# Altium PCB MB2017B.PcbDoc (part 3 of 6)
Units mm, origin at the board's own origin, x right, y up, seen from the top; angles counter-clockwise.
Board outline 148.19 x 169.19 mm, 4 copper layers (Top Layer, Mid Layer 1, Mid Layer 2, Bottom Layer), stack 1.498 mm thick; 458 components, 208 nets, 1223 pads, 6162 vias.
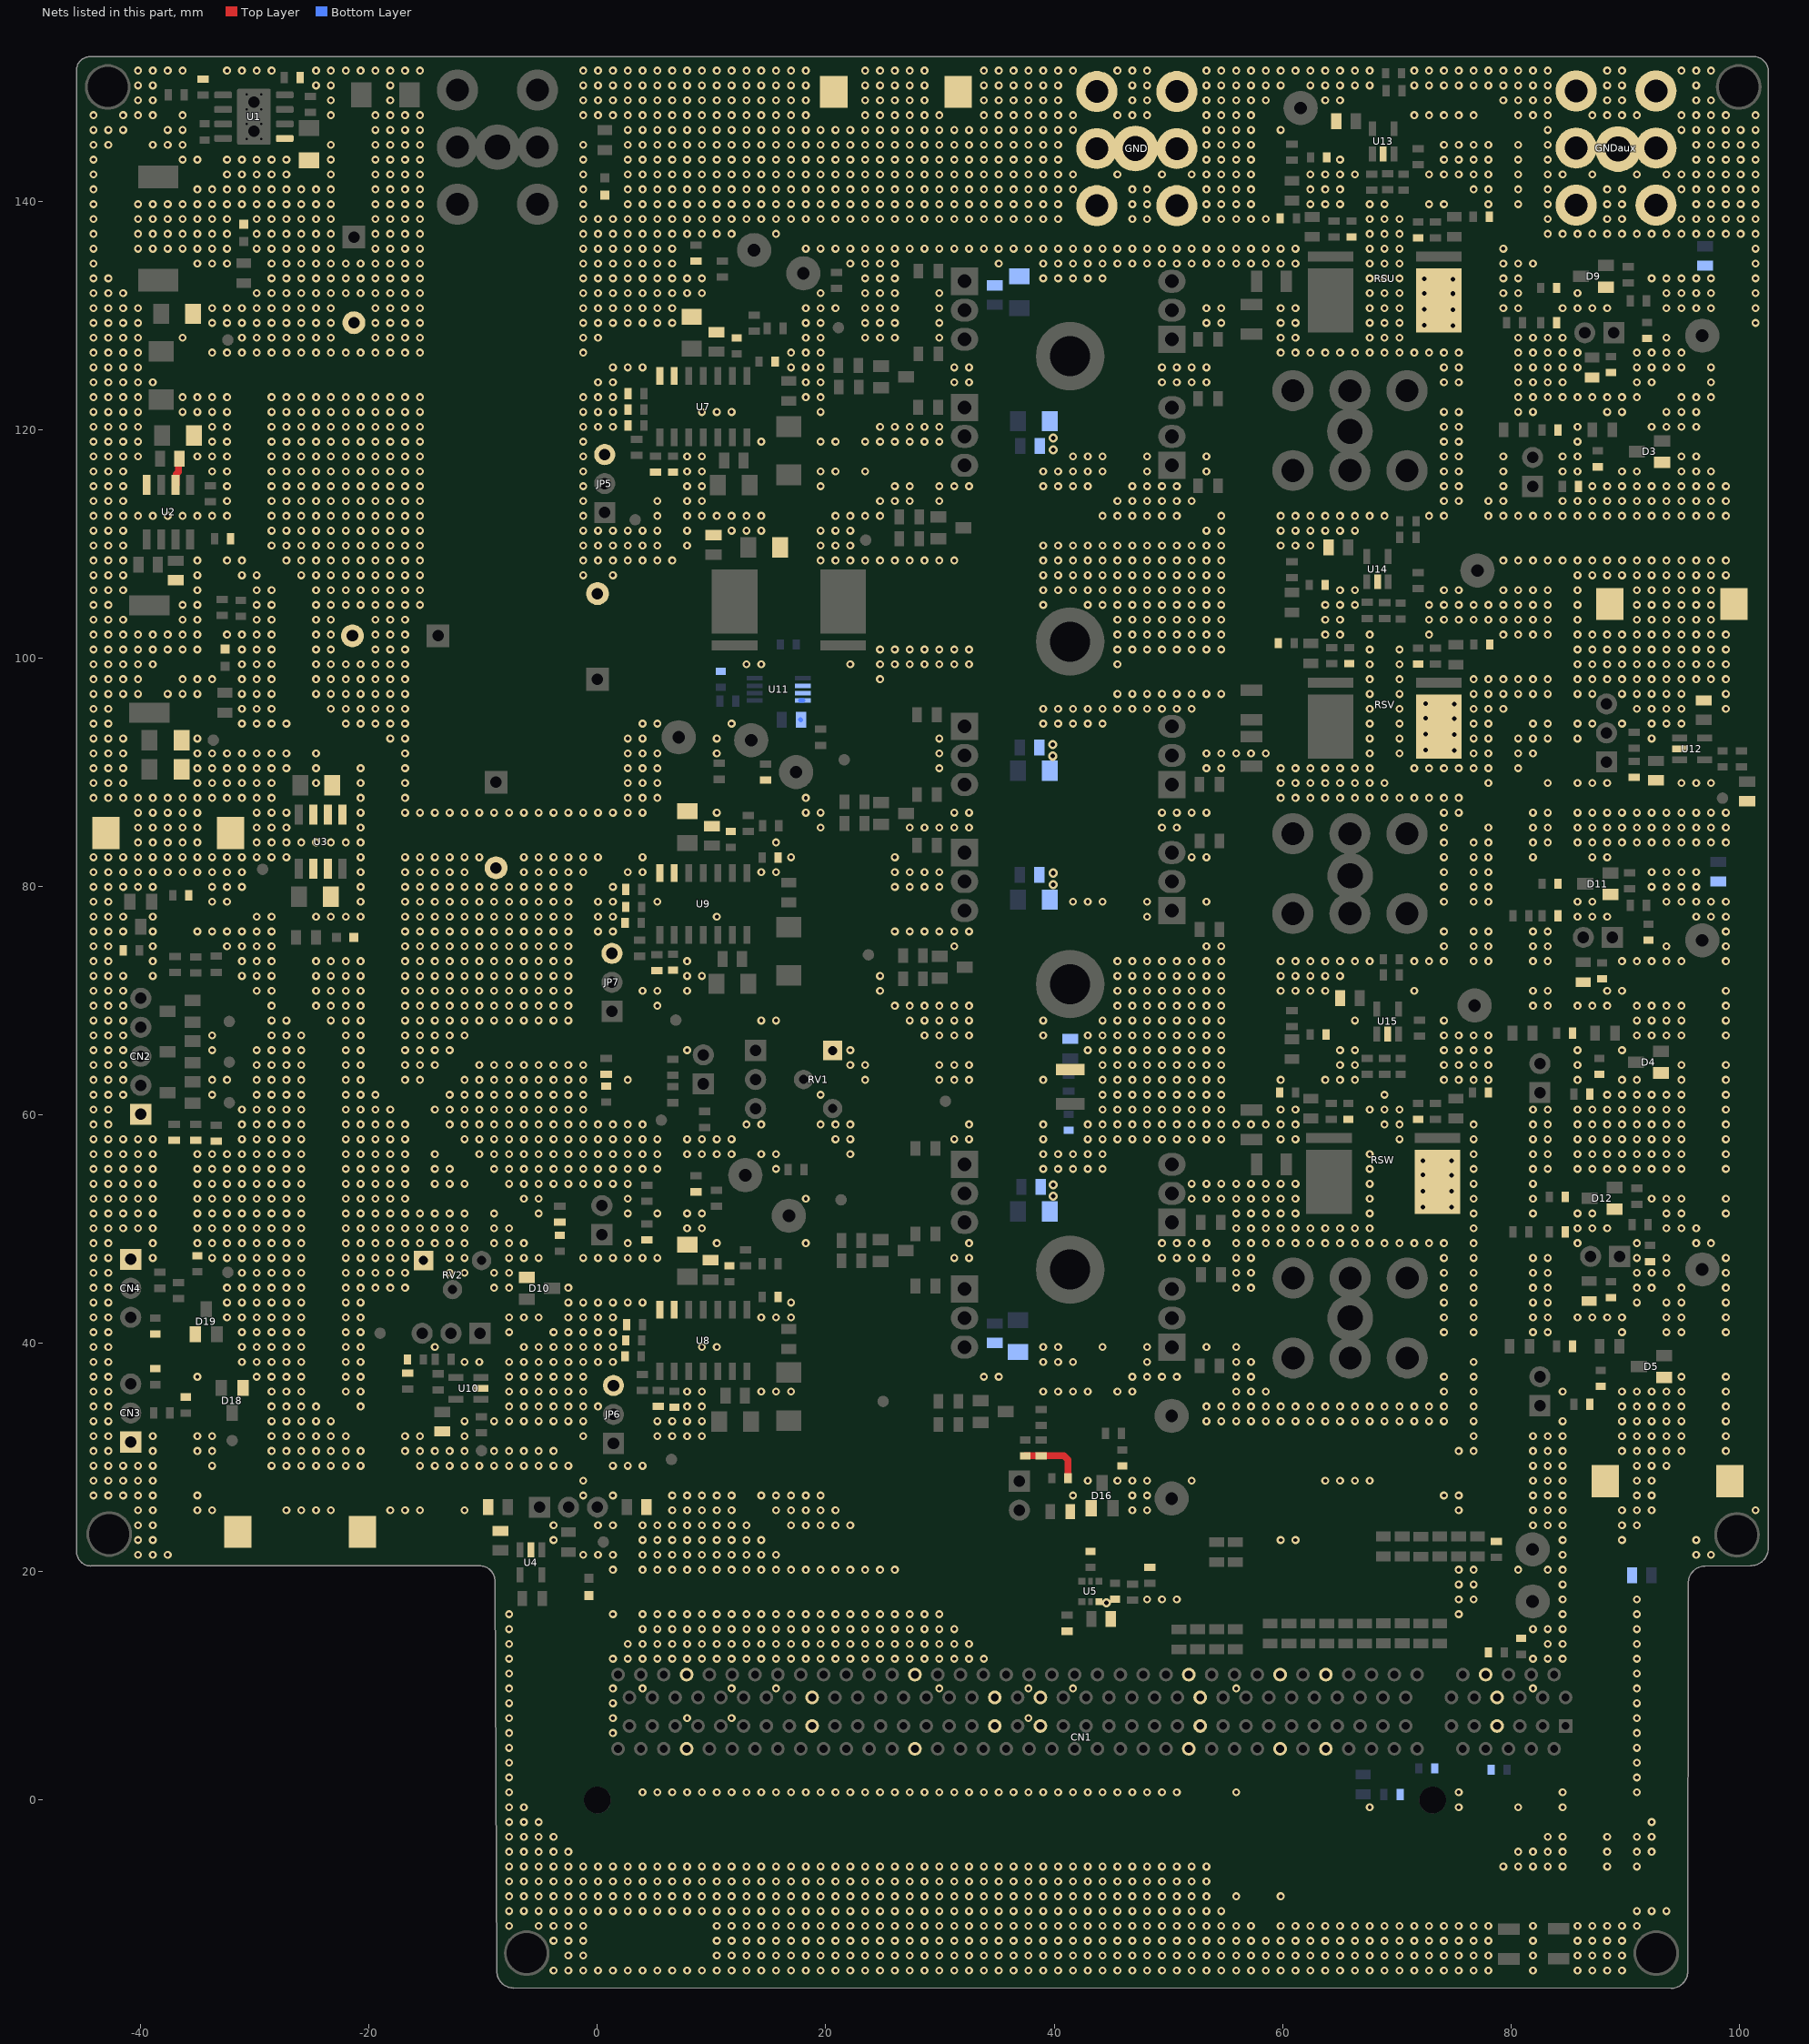
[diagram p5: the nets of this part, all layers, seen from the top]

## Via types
v1: diameter 0.7, hole 0.35, Top Layer to Bottom Layer, tented both sides, 5935 vias
v2: diameter 0.8, hole 0.4, Top Layer to Bottom Layer, tented both sides, 216 vias
v3: diameter 1, hole 0.5, Top Layer to Bottom Layer, tented both sides, 9 vias
v4: diameter 0.8, hole 0.4, Top Layer to Bottom Layer, 2 vias

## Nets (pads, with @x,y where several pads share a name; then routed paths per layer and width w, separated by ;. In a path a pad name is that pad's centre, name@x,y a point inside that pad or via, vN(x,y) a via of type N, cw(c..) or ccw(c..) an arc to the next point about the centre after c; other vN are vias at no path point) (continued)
GND: (continued)
  other v1: -3.853,-14.916 -2.553,-14.916 -1.253,-14.916 0.047,-14.916 1.347,-14.916 2.647,-14.916 3.947,-14.916 5.247,-14.916 6.547,-14.916 7.847,-14.916 9.147,-14.916 10.447,-14.916 11.747,-14.916 13.047,-14.916 14.347,-14.916 15.647,-14.916 16.947,-14.916 18.247,-14.916 19.547,-14.916 20.847,-14.916 22.147,-14.916 23.447,-14.916 24.747,-14.916 26.047,-14.916 27.347,-14.916 28.647,-14.916 29.947,-14.916 31.247,-14.916 32.547,-14.916 33.847,-14.916 35.147,-14.916 36.447,-14.916 37.747,-14.916 39.047,-14.916 40.347,-14.916 41.647,-14.916 42.947,-14.916 44.247,-14.916 45.547,-14.916 46.847,-14.916 48.147,-14.916 49.447,-14.916 50.747,-14.916 52.047,-14.916 53.347,-14.916 54.647,-14.916 55.947,-14.916 57.247,-14.916 58.547,-14.916 59.847,-14.916 61.147,-14.916 62.447,-14.916 63.747,-14.916 65.047,-14.916 66.347,-14.916 67.647,-14.916 68.947,-14.916 70.247,-14.916 71.547,-14.916 72.847,-14.916 74.147,-14.916 75.447,-14.916 76.747,-14.916 78.047,-14.916 81.947,-14.916 85.847,-14.916 87.147,-14.916 88.447,-14.916 89.747,-14.916 -2.553,-13.616 -1.253,-13.616 10.447,-13.616 11.747,-13.616 13.047,-13.616 14.347,-13.616 15.647,-13.616 16.947,-13.616 18.247,-13.616 19.547,-13.616 20.847,-13.616 22.147,-13.616 23.447,-13.616 24.747,-13.616 26.047,-13.616 27.347,-13.616 28.647,-13.616 29.947,-13.616 31.247,-13.616 32.547,-13.616 33.847,-13.616 35.147,-13.616 36.447,-13.616 37.747,-13.616 39.047,-13.616 40.347,-13.616 41.647,-13.616 42.947,-13.616 44.247,-13.616 45.547,-13.616 46.847,-13.616 48.147,-13.616 49.447,-13.616 50.747,-13.616 52.047,-13.616 53.347,-13.616 54.647,-13.616 55.947,-13.616 57.247,-13.616 58.547,-13.616 59.847,-13.616 61.147,-13.616 62.447,-13.616 63.747,-13.616 65.047,-13.616 66.347,-13.616 67.647,-13.616 68.947,-13.616 70.247,-13.616 71.547,-13.616 72.847,-13.616 74.147,-13.616 75.447,-13.616 76.747,-13.616 78.047,-13.616 81.947,-13.616 85.847,-13.616 87.147,-13.616 88.447,-13.616 89.747,-13.616 -3.853,-12.316 -2.553,-12.316 -1.253,-12.316 10.447,-12.316 11.747,-12.316 13.047,-12.316 14.347,-12.316 15.647,-12.316 16.947,-12.316 18.247,-12.316 19.547,-12.316 20.847,-12.316 22.147,-12.316 23.447,-12.316 24.747,-12.316 26.047,-12.316 27.347,-12.316 28.647,-12.316 29.947,-12.316 31.247,-12.316 32.547,-12.316 33.847,-12.316 35.147,-12.316 36.447,-12.316 37.747,-12.316 39.047,-12.316 40.347,-12.316 41.647,-12.316 42.947,-12.316 44.247,-12.316 45.547,-12.316 46.847,-12.316 48.147,-12.316 49.447,-12.316 50.747,-12.316 52.047,-12.316 53.347,-12.316 54.647,-12.316 55.947,-12.316 57.247,-12.316 58.547,-12.316 59.847,-12.316 61.147,-12.316 62.447,-12.316 63.747,-12.316 65.047,-12.316 66.347,-12.316 67.647,-12.316 68.947,-12.316 70.247,-12.316 71.547,-12.316 72.847,-12.316 74.147,-12.316 75.447,-12.316 76.747,-12.316 78.047,-12.316 81.947,-12.316 85.847,-12.316 87.147,-12.316 88.447,-12.316 89.747,-12.316 -7.753,-11.016 -5.153,-11.016 -3.853,-11.016 -2.553,-11.016 -1.253,-11.016 10.447,-11.016 11.747,-11.016 13.047,-11.016 14.347,-11.016 15.647,-11.016 16.947,-11.016 18.247,-11.016 19.547,-11.016 20.847,-11.016 22.147,-11.016 23.447,-11.016 24.747,-11.016 26.047,-11.016 27.347,-11.016 28.647,-11.016 29.947,-11.016 31.247,-11.016 32.547,-11.016 33.847,-11.016 35.147,-11.016 36.447,-11.016 37.747,-11.016 39.047,-11.016 40.347,-11.016 41.647,-11.016 42.947,-11.016 44.247,-11.016 45.547,-11.016 46.847,-11.016 48.147,-11.016 49.447,-11.016 50.747,-11.016 52.047,-11.016 53.347,-11.016 54.647,-11.016 55.947,-11.016 57.247,-11.016 59.847,-11.016 61.147,-11.016 62.447,-11.016 63.747,-11.016 65.047,-11.016 66.347,-11.016 67.647,-11.016 68.947,-11.016 70.247,-11.016 71.547,-11.016 72.847,-11.016 74.147,-11.016 75.447,-11.016 76.747,-11.016 78.047,-11.016 81.947,-11.016 85.847,-11.016 87.147,-11.016 88.447,-11.016 89.747,-11.016 91.047,-11.016 -7.753,-9.716 -6.453,-9.716 -5.153,-9.716 -3.853,-9.716 -2.553,-9.716 -1.253,-9.716 0.047,-9.716 1.347,-9.716 2.647,-9.716 3.947,-9.716 5.247,-9.716 6.547,-9.716 7.847,-9.716 9.147,-9.716 10.447,-9.716 11.747,-9.716 13.047,-9.716 14.347,-9.716 15.647,-9.716 16.947,-9.716 18.247,-9.716 19.547,-9.716 20.847,-9.716 22.147,-9.716 23.447,-9.716 24.747,-9.716 26.047,-9.716 27.347,-9.716 28.647,-9.716 29.947,-9.716 31.247,-9.716 32.547,-9.716 33.847,-9.716 35.147,-9.716 36.447,-9.716 37.747,-9.716 39.047,-9.716 40.347,-9.716 41.647,-9.716 42.947,-9.716 44.247,-9.716 45.547,-9.716 46.847,-9.716 48.147,-9.716 49.447,-9.716 50.747,-9.716 52.047,-9.716 53.347,-9.716 54.647,-9.716 91.047,-9.716 92.347,-9.716 93.647,-9.716 -7.753,-8.416 -6.453,-8.416 -5.153,-8.416 -3.853,-8.416 -2.553,-8.416 -1.253,-8.416 0.047,-8.416 1.347,-8.416 2.647,-8.416 3.947,-8.416 5.247,-8.416 6.547,-8.416 7.847,-8.416 9.147,-8.416 10.447,-8.416 11.747,-8.416 13.047,-8.416 14.347,-8.416 15.647,-8.416 16.947,-8.416 18.247,-8.416 19.547,-8.416 20.847,-8.416 22.147,-8.416 23.447,-8.416 24.747,-8.416 26.047,-8.416 27.347,-8.416 28.647,-8.416 29.947,-8.416 31.247,-8.416 32.547,-8.416 33.847,-8.416 35.147,-8.416 36.447,-8.416 37.747,-8.416 39.047,-8.416 40.347,-8.416 41.647,-8.416 42.947,-8.416 44.247,-8.416 45.547,-8.416 46.847,-8.416 48.147,-8.416 49.447,-8.416 50.747,-8.416 52.047,-8.416 53.347,-8.416 55.947,-8.416 59.847,-8.416 -7.753,-7.116 -6.453,-7.116 -5.153,-7.116 -3.853,-7.116 -2.553,-7.116 -1.253,-7.116 0.047,-7.116 1.347,-7.116 2.647,-7.116 3.947,-7.116 5.247,-7.116 6.547,-7.116 7.847,-7.116 9.147,-7.116 10.447,-7.116 11.747,-7.116 13.047,-7.116 14.347,-7.116 15.647,-7.116 16.947,-7.116 18.247,-7.116 19.547,-7.116 20.847,-7.116 22.147,-7.116 23.447,-7.116 24.747,-7.116 26.047,-7.116 27.347,-7.116 28.647,-7.116 29.947,-7.116 31.247,-7.116 32.547,-7.116 33.847,-7.116 35.147,-7.116 36.447,-7.116 37.747,-7.116 39.047,-7.116 40.347,-7.116 41.647,-7.116 42.947,-7.116 44.247,-7.116 45.547,-7.116 46.847,-7.116 48.147,-7.116 49.447,-7.116 50.747,-7.116 52.047,-7.116 53.347,-7.116 -7.753,-5.816 -6.453,-5.816 -5.153,-5.816 -3.853,-5.816 -2.553,-5.816 -1.253,-5.816 0.047,-5.816 1.347,-5.816 2.647,-5.816 3.947,-5.816 5.247,-5.816 6.547,-5.816 7.847,-5.816 9.147,-5.816 10.447,-5.816 11.747,-5.816 13.047,-5.816 14.347,-5.816 15.647,-5.816 16.947,-5.816 18.247,-5.816 19.547,-5.816 20.847,-5.816 22.147,-5.816 23.447,-5.816 24.747,-5.816 26.047,-5.816 27.347,-5.816 28.647,-5.816 29.947,-5.816 31.247,-5.816 32.547,-5.816 33.847,-5.816 35.147,-5.816 36.447,-5.816 37.747,-5.816 39.047,-5.816 40.347,-5.816 41.647,-5.816 42.947,-5.816 44.247,-5.816 45.547,-5.816 46.847,-5.816 48.147,-5.816 49.447,-5.816 50.747,-5.816 52.047,-5.816 53.347,-5.816 79.347,-5.816 80.647,-5.816 81.947,-5.816 83.247,-5.816 84.547,-5.816 88.447,-5.816 91.047,-5.816 -7.753,-4.516 -6.453,-4.516 -5.153,-4.516 -3.853,-4.516 -2.553,-4.516 80.647,-4.516 81.947,-4.516 83.247,-4.516 84.547,-4.516 88.447,-4.516 91.047,-4.516 92.347,-4.516 -7.753,-3.216 -6.453,-3.216 -5.153,-3.216 -3.853,-3.216 83.247,-3.216 84.547,-3.216 88.447,-3.216 91.047,-3.216 92.347,-3.216 -7.753,-1.916 -6.453,-1.916 -5.153,-1.916 92.347,-1.916 -7.753,-0.616 -6.453,-0.616 67.647,-0.616 75.447,-0.616 80.647,-0.616 84.547,-0.616 -7.753,0.684 3.947,0.684 5.247,0.684 6.547,0.684 7.847,0.684 9.147,0.684 10.447,0.684 11.747,0.684 13.047,0.684 14.347,0.684 15.647,0.684 16.947,0.684 18.247,0.684 19.547,0.684 20.847,0.684 22.147,0.684 23.447,0.684 24.747,0.684 26.047,0.684 27.347,0.684 28.647,0.684 29.947,0.684 31.247,0.684 32.547,0.684 33.847,0.684 35.147,0.684 36.447,0.684 37.747,0.684 39.047,0.684 40.347,0.684 41.647,0.684 42.947,0.684 44.247,0.684 45.547,0.684 46.847,0.684 48.147,0.684 49.447,0.684 50.747,0.684 55.947,0.684 75.447,0.684 84.547,0.684 91.047,0.684 -7.753,1.984 91.047,1.984 -7.753,3.284 91.047,3.284 -7.753,4.584 91.047,4.584 -7.753,5.884 1.347,5.884 91.047,5.884 -7.753,7.184 1.347,7.184 7.847,7.184 11.747,7.184 37.747,7.184 91.047,7.184 -7.753,8.484 1.347,8.484 91.047,8.484 -7.753,9.784 1.347,9.784 3.947,9.784 11.747,9.784 15.647,9.784 29.947,9.784 37.747,9.784 41.647,9.784 55.947,9.784 81.947,9.784 91.047,9.784 -7.753,11.084 91.047,11.084 -7.753,12.384 1.347,12.384 2.647,12.384 3.947,12.384 5.247,12.384 6.547,12.384 7.847,12.384 9.147,12.384 10.447,12.384 11.747,12.384 13.047,12.384 14.347,12.384 15.647,12.384 16.947,12.384 18.247,12.384 19.547,12.384 20.847,12.384 22.147,12.384 23.447,12.384 24.747,12.384 26.047,12.384 27.347,12.384 28.647,12.384 29.947,12.384 31.247,12.384 32.547,12.384 33.847,12.384 81.947,12.384 83.247,12.384 84.547,12.384 91.047,12.384 -7.753,13.684 2.647,13.684 3.947,13.684 5.247,13.684 6.547,13.684 7.847,13.684 9.147,13.684 10.447,13.684 11.747,13.684 13.047,13.684 14.347,13.684 15.647,13.684 16.947,13.684 18.247,13.684 19.547,13.684 20.847,13.684 22.147,13.684 23.447,13.684 24.747,13.684 26.047,13.684 27.347,13.684 28.647,13.684 29.947,13.684 31.247,13.684 32.547,13.684 83.247,13.684 84.547,13.684 91.047,13.684 -7.753,14.984 3.947,14.984 5.247,14.984 6.547,14.984 7.847,14.984 9.147,14.984 10.447,14.984 11.747,14.984 13.047,14.984 14.347,14.984 15.647,14.984 16.947,14.984 18.247,14.984 19.547,14.984 20.847,14.984 22.147,14.984 23.447,14.984 24.747,14.984 26.047,14.984 27.347,14.984 28.647,14.984 29.947,14.984 31.247,14.984 81.947,14.984 83.247,14.984 84.547,14.984 91.047,14.984 -7.753,16.284 1.347,16.284 3.947,16.284 5.247,16.284 6.547,16.284 7.847,16.284 9.147,16.284 10.447,16.284 11.747,16.284 13.047,16.284 14.347,16.284 15.647,16.284 16.947,16.284 18.247,16.284 19.547,16.284 20.847,16.284 22.147,16.284 23.447,16.284 24.747,16.284 26.047,16.284 27.347,16.284 28.647,16.284 29.947,16.284 75.447,16.284 84.547,16.284 91.047,16.284 48.147,17.584 49.447,17.584 50.747,17.584 75.447,17.584 76.747,17.584 84.547,17.584 91.047,17.584 75.447,18.884 76.747,18.884 84.547,18.884 1.347,20.184 3.947,20.184 5.247,20.184 6.547,20.184 7.847,20.184 9.147,20.184 10.447,20.184 11.747,20.184 13.047,20.184 14.347,20.184 15.647,20.184 16.947,20.184 18.247,20.184 19.547,20.184 20.847,20.184 22.147,20.184 23.447,20.184 24.747,20.184 26.047,20.184 75.447,20.184 76.747,20.184 80.647,20.184 83.247,20.184 84.547,20.184 -40.253,21.484 -38.953,21.484 -37.653,21.484 -1.253,21.484 0.047,21.484 1.347,21.484 3.947,21.484 5.247,21.484 6.547,21.484 7.847,21.484 9.147,21.484 10.447,21.484 11.747,21.484 13.047,21.484 14.347,21.484 15.647,21.484 84.547,21.484 96.247,21.484 97.547,21.484 -40.253,22.784 -38.953,22.784 -3.853,22.784 3.947,22.784 5.247,22.784 6.547,22.784 7.847,22.784 9.147,22.784 10.447,22.784 11.747,22.784 13.047,22.784 14.347,22.784 59.847,22.784 61.147,22.784 84.547,22.784 89.747,22.784 96.247,22.784 -40.253,24.084 -38.953,24.084 -3.853,24.084 0.047,24.084 1.347,24.084 3.947,24.084 5.247,24.084 6.547,24.084 7.847,24.084 9.147,24.084 10.447,24.084 11.747,24.084 13.047,24.084 16.947,24.084 18.247,24.084 19.547,24.084 20.847,24.084 22.147,24.084 81.947,24.084 83.247,24.084 84.547,24.084 89.747,24.084 91.047,24.084 -40.253,25.384 -38.953,25.384 -35.053,25.384 -33.753,25.384 -27.253,25.384 -25.953,25.384 -24.653,25.384 -23.353,25.384 -18.153,25.384 -16.853,25.384 -15.553,25.384 -11.653,25.384 6.547,25.384 7.847,25.384 9.147,25.384 10.447,25.384 11.747,25.384 15.647,25.384 16.947,25.384 18.247,25.384 19.547,25.384 20.847,25.384 46.847,25.384 48.147,25.384 75.447,25.384 81.947,25.384 83.247,25.384 84.547,25.384 89.747,25.384 91.047,25.384 92.347,25.384 101.447,25.384 -44.153,26.684 -42.853,26.684 -41.553,26.684 -40.253,26.684 -38.953,26.684 -35.053,26.684 -1.253,26.684 1.347,26.684 6.547,26.684 7.847,26.684 9.147,26.684 10.447,26.684 11.747,26.684 14.347,26.684 15.647,26.684 16.947,26.684 18.247,26.684 19.547,26.684 41.647,26.684 46.847,26.684 48.147,26.684 74.147,26.684 75.447,26.684 81.947,26.684 83.247,26.684 84.547,26.684 91.047,26.684 92.347,26.684 -44.153,27.984 -42.853,27.984 -41.553,27.984 -40.253,27.984 -38.953,27.984 -1.253,27.984 42.947,27.984 45.547,27.984 46.847,27.984 48.147,27.984 52.047,27.984 63.747,27.984 65.047,27.984 66.347,27.984 67.647,27.984 81.947,27.984 83.247,27.984 84.547,27.984 91.047,27.984 92.347,27.984 -44.153,29.284 -42.853,29.284 -41.553,29.284 -40.253,29.284 -38.953,29.284 -33.753,29.284 -28.553,29.284 -27.253,29.284 -25.953,29.284 -24.653,29.284 -23.353,29.284 -22.053,29.284 -20.753,29.284 -15.553,29.284 -14.253,29.284 -12.953,29.284 -11.653,29.284 -10.353,29.284 -9.053,29.284 -7.753,29.284 -6.453,29.284 -5.153,29.284 -3.853,29.284 -2.553,29.284 1.347,29.284 2.647,29.284 3.947,29.284 81.947,29.284 83.247,29.284 84.547,29.284 91.047,29.284 92.347,29.284 93.647,29.284 -44.153,30.584 -42.853,30.584 -38.953,30.584 -35.053,30.584 -33.753,30.584 -28.553,30.584 -27.253,30.584 -25.953,30.584 -24.653,30.584 -23.353,30.584 -22.053,30.584 -20.753,30.584 -16.853,30.584 -15.553,30.584 -14.253,30.584 -12.953,30.584 -11.653,30.584 -9.053,30.584 -7.753,30.584 -6.453,30.584 -5.153,30.584 -3.853,30.584 75.447,30.584 76.747,30.584 81.947,30.584 83.247,30.584 84.547,30.584 89.747,30.584 91.047,30.584 92.347,30.584 93.647,30.584 94.947,30.584 98.847,30.584 -44.153,31.884 -42.853,31.884 -38.953,31.884 -35.053,31.884 -33.753,31.884 -28.553,31.884 -27.253,31.884 -25.953,31.884 -24.653,31.884 -23.353,31.884 -22.053,31.884 -16.853,31.884 -15.553,31.884 -11.653,31.884 -1.253,31.884 5.247,31.884 6.547,31.884 7.847,31.884 9.147,31.884 76.747,31.884 81.947,31.884 83.247,31.884 84.547,31.884 89.747,31.884 91.047,31.884 92.347,31.884 93.647,31.884 94.947,31.884 98.847,31.884 -44.153,33.184 -42.853,33.184 -28.553,33.184 -27.253,33.184 -25.953,33.184 -24.653,33.184 -23.353,33.184 -11.653,33.184 -9.053,33.184 -7.753,33.184 -6.453,33.184 -5.153,33.184 -3.853,33.184 -2.553,33.184 -1.253,33.184 5.247,33.184 6.547,33.184 7.847,33.184 9.147,33.184 53.347,33.184 54.647,33.184 55.947,33.184 57.247,33.184 58.547,33.184 59.847,33.184 61.147,33.184 62.447,33.184 63.747,33.184 65.047,33.184 66.347,33.184 67.647,33.184 68.947,33.184 70.247,33.184 71.547,33.184 72.847,33.184 74.147,33.184 76.747,33.184 84.547,33.184 89.747,33.184 91.047,33.184 92.347,33.184 93.647,33.184 94.947,33.184 98.847,33.184 -44.153,34.484 -42.853,34.484 -28.553,34.484 -27.253,34.484 -25.953,34.484 -24.653,34.484 -20.753,34.484 -7.753,34.484 -6.453,34.484 -5.153,34.484 -3.853,34.484 -2.553,34.484 -1.253,34.484 0.047,34.484 7.847,34.484 9.147,34.484 53.347,34.484 54.647,34.484 55.947,34.484 57.247,34.484 58.547,34.484 59.847,34.484 61.147,34.484 62.447,34.484 63.747,34.484 65.047,34.484 66.347,34.484 67.647,34.484 68.947,34.484 70.247,34.484 71.547,34.484 72.847,34.484 74.147,34.484 76.747,34.484 89.747,34.484 91.047,34.484 92.347,34.484 93.647,34.484 94.947,34.484 98.847,34.484 -44.153,35.784 -42.853,35.784 -28.553,35.784 -27.253,35.784 -25.953,35.784 -22.053,35.784 -20.753,35.784 -7.753,35.784 -6.453,35.784 -5.153,35.784 -3.853,35.784 -2.553,35.784 -1.253,35.784 7.847,35.784 9.147,35.784 14.347,35.784 15.647,35.784 16.947,35.784 39.047,35.784 40.347,35.784 41.647,35.784 42.947,35.784 45.547,35.784 46.847,35.784 55.947,35.784 57.247,35.784 58.547,35.784 74.147,35.784 76.747,35.784 84.547,35.784 89.747,35.784 91.047,35.784 92.347,35.784 93.647,35.784 94.947,35.784 98.847,35.784 -44.153,37.084 -42.853,37.084 -35.053,37.084 -29.853,37.084 -28.553,37.084 -27.253,37.084 -25.953,37.084 -22.053,37.084 -20.753,37.084 -7.753,37.084 -6.453,37.084 -5.153,37.084 -3.853,37.084 -2.553,37.084 -1.253,37.084 33.847,37.084 35.147,37.084 46.847,37.084 48.147,37.084 49.447,37.084 50.747,37.084 55.947,37.084 57.247,37.084 74.147,37.084 76.747,37.084 94.947,37.084 98.847,37.084 -44.153,38.384 -42.853,38.384 -31.153,38.384 -29.853,38.384 -28.553,38.384 -27.253,38.384 -25.953,38.384 -22.053,38.384 -20.753,38.384 -11.653,38.384 -10.353,38.384 -7.753,38.384 -6.453,38.384 -5.153,38.384 -3.853,38.384 -2.553,38.384 -1.253,38.384 0.047,38.384 1.347,38.384 39.047,38.384 40.347,38.384 41.647,38.384 48.147,38.384 55.947,38.384 57.247,38.384 76.747,38.384 -44.153,39.684 -42.853,39.684 -31.153,39.684 -29.853,39.684 -28.553,39.684 -27.253,39.684 -25.953,39.684 -22.053,39.684 -20.753,39.684 -14.253,39.684 -6.453,39.684 -5.153,39.684 -3.853,39.684 -2.553,39.684 -1.253,39.684 0.047,39.684 1.347,39.684 9.147,39.684 10.447,39.684 39.047,39.684 40.347,39.684 44.247,39.684 48.147,39.684 53.347,39.684 55.947,39.684 -44.153,40.984 -42.853,40.984 -31.153,40.984 -29.853,40.984 -28.553,40.984 -27.253,40.984 -25.953,40.984 -22.053,40.984 -20.753,40.984 -7.753,40.984 -3.853,40.984 -2.553,40.984 -1.253,40.984 0.047,40.984 1.347,40.984 74.147,40.984 76.747,40.984 81.947,40.984 83.247,40.984 89.747,40.984 93.647,40.984 94.947,40.984 98.847,40.984 -44.153,42.284 -42.853,42.284 -32.453,42.284 -31.153,42.284 -29.853,42.284 -28.553,42.284 -27.253,42.284 -25.953,42.284 -22.053,42.284 -20.753,42.284 -7.753,42.284 -6.453,42.284 -5.153,42.284 -2.553,42.284 -1.253,42.284 0.047,42.284 1.347,42.284 14.347,42.284 15.647,42.284 16.947,42.284 74.147,42.284 76.747,42.284 81.947,42.284 83.247,42.284 85.847,42.284 87.147,42.284 88.447,42.284 89.747,42.284 93.647,42.284 94.947,42.284 98.847,42.284 -44.153,43.584 -42.853,43.584 -32.453,43.584 -31.153,43.584 -29.853,43.584 -28.553,43.584 -27.253,43.584 -25.953,43.584 -22.053,43.584 -20.753,43.584 -2.553,43.584 -1.253,43.584 0.047,43.584 1.347,43.584 2.647,43.584 3.947,43.584 16.947,43.584 74.147,43.584 76.747,43.584 81.947,43.584 83.247,43.584 91.047,43.584 93.647,43.584 94.947,43.584 98.847,43.584 -44.153,44.884 -42.853,44.884 -32.453,44.884 -31.153,44.884 -29.853,44.884 -28.553,44.884 -27.253,44.884 -25.953,44.884 -22.053,44.884 -20.753,44.884 -19.453,44.884 -18.153,44.884 -16.853,44.884 -9.053,44.884 -7.753,44.884 -2.553,44.884 55.947,44.884 57.247,44.884 74.147,44.884 76.747,44.884 81.947,44.884 83.247,44.884 91.047,44.884 92.347,44.884 94.947,44.884 98.847,44.884 -44.153,46.184 -42.853,46.184 -31.153,46.184 -29.853,46.184 -28.553,46.184 -27.253,46.184 -25.953,46.184 -22.053,46.184 -20.753,46.184 -19.453,46.184 -18.153,46.184 -16.853,46.184 -12.953,46.184 -11.653,46.184 -9.053,46.184 -7.753,46.184 55.947,46.184 57.247,46.184 74.147,46.184 76.747,46.184 81.947,46.184 83.247,46.184 91.047,46.184 92.347,46.184 93.647,46.184 98.847,46.184 -44.153,47.484 -42.853,47.484 -38.953,47.484 -33.753,47.484 -32.453,47.484 -31.153,47.484 -29.853,47.484 -28.553,47.484 -27.253,47.484 -25.953,47.484 -22.053,47.484 -20.753,47.484 -19.453,47.484 -18.153,47.484 -16.853,47.484 -12.953,47.484 -11.653,47.484 -7.753,47.484 -6.453,47.484 -5.153,47.484 -1.253,47.484 0.047,47.484 1.347,47.484 2.647,47.484 3.947,47.484 5.247,47.484 31.247,47.484 32.547,47.484 49.447,47.484 50.747,47.484 52.047,47.484 53.347,47.484 55.947,47.484 57.247,47.484 74.147,47.484 76.747,47.484 81.947,47.484 83.247,47.484 91.047,47.484 93.647,47.484 98.847,47.484 -44.153,48.784 -42.853,48.784 -38.953,48.784 -35.053,48.784 -33.753,48.784 -32.453,48.784 -31.153,48.784 -29.853,48.784 -28.553,48.784 -27.253,48.784 -25.953,48.784 -22.053,48.784 -20.753,48.784 -19.453,48.784 -18.153,48.784 -16.853,48.784 -15.553,48.784 -14.253,48.784 -12.953,48.784 -11.653,48.784 -9.053,48.784 -7.753,48.784 -6.453,48.784 2.647,48.784 10.447,48.784 18.247,48.784 32.547,48.784 49.447,48.784 50.747,48.784 52.047,48.784 53.347,48.784 55.947,48.784 57.247,48.784 58.547,48.784 59.847,48.784 61.147,48.784 62.447,48.784 63.747,48.784 65.047,48.784 66.347,48.784 67.647,48.784 68.947,48.784 70.247,48.784 71.547,48.784 72.847,48.784 74.147,48.784 76.747,48.784 85.847,48.784 91.047,48.784 96.247,48.784 97.547,48.784 -44.153,50.084 -42.853,50.084 -41.553,50.084 -40.253,50.084 -38.953,50.084 -35.053,50.084 -33.753,50.084 -32.453,50.084 -31.153,50.084 -29.853,50.084 -28.553,50.084 -27.253,50.084 -25.953,50.084 -22.053,50.084 -20.753,50.084 -19.453,50.084 -18.153,50.084 -16.853,50.084 -15.553,50.084 -14.253,50.084 -12.953,50.084 -11.653,50.084 -9.053,50.084 -7.753,50.084 7.847,50.084 9.147,50.084 55.947,50.084 57.247,50.084 58.547,50.084 59.847,50.084 61.147,50.084 62.447,50.084 63.747,50.084 65.047,50.084 66.347,50.084 67.647,50.084 76.747,50.084 85.847,50.084 87.147,50.084 88.447,50.084 93.647,50.084 94.947,50.084 96.247,50.084 -44.153,51.384 -42.853,51.384 -41.553,51.384 -40.253,51.384 -38.953,51.384 -35.053,51.384 -33.753,51.384 -32.453,51.384 -31.153,51.384 -29.853,51.384 -28.553,51.384 -27.253,51.384 -25.953,51.384 -22.053,51.384 -20.753,51.384 -19.453,51.384 -18.153,51.384 -16.853,51.384 -15.553,51.384 -14.253,51.384 -12.953,51.384 -11.653,51.384 -9.053,51.384 -5.153,51.384 2.647,51.384 5.247,51.384 7.847,51.384 9.147,51.384 55.947,51.384 57.247,51.384 58.547,51.384 59.847,51.384 61.147,51.384 67.647,51.384 76.747,51.384 81.947,51.384 85.847,51.384 87.147,51.384 93.647,51.384 94.947,51.384 98.847,51.384 -44.153,52.684 -42.853,52.684 -41.553,52.684 -40.253,52.684 -38.953,52.684 -35.053,52.684 -33.753,52.684 -32.453,52.684 -31.153,52.684 -29.853,52.684 -28.553,52.684 -27.253,52.684 -25.953,52.684 -22.053,52.684 -20.753,52.684 -19.453,52.684 -18.153,52.684 -16.853,52.684 -6.453,52.684 -5.153,52.684 2.647,52.684 18.247,52.684 52.047,52.684 53.347,52.684 54.647,52.684 55.947,52.684 57.247,52.684 58.547,52.684 59.847,52.684 61.147,52.684 67.647,52.684 76.747,52.684 81.947,52.684 92.347,52.684 93.647,52.684 94.947,52.684 98.847,52.684 -44.153,53.984 -42.853,53.984 -41.553,53.984 -40.253,53.984 -38.953,53.984 -35.053,53.984 -33.753,53.984 -32.453,53.984 -31.153,53.984 -29.853,53.984 -28.553,53.984 -27.253,53.984 -25.953,53.984 -22.053,53.984 -20.753,53.984 -19.453,53.984 -18.153,53.984 -16.853,53.984 -14.253,53.984 -12.953,53.984 -11.653,53.984 -7.753,53.984 -6.453,53.984 -5.153,53.984 -3.853,53.984 -2.553,53.984 -1.253,53.984 0.047,53.984 1.347,53.984 2.647,53.984 52.047,53.984 53.347,53.984 54.647,53.984 55.947,53.984 57.247,53.984 58.547,53.984 59.847,53.984 61.147,53.984 67.647,53.984 76.747,53.984 81.947,53.984 -44.153,55.284 -42.853,55.284 -41.553,55.284 -40.253,55.284 -38.953,55.284 -35.053,55.284 -33.753,55.284 -32.453,55.284 -31.153,55.284 -29.853,55.284 -28.553,55.284 -27.253,55.284 -25.953,55.284 -22.053,55.284 -20.753,55.284 -19.453,55.284 -18.153,55.284 -16.853,55.284 -14.253,55.284 -12.953,55.284 -9.053,55.284 -7.753,55.284 -6.453,55.284 -5.153,55.284 -3.853,55.284 -2.553,55.284 -1.253,55.284 0.047,55.284 1.347,55.284 2.647,55.284 3.947,55.284 5.247,55.284 15.647,55.284 39.047,55.284 40.347,55.284 41.647,55.284 42.947,55.284 44.247,55.284 67.647,55.284 76.747,55.284 81.947,55.284 83.247,55.284 85.847,55.284 87.147,55.284 88.447,55.284 89.747,55.284 91.047,55.284 92.347,55.284 93.647,55.284 94.947,55.284 98.847,55.284 -44.153,56.584 -42.853,56.584 -41.553,56.584 -40.253,56.584 -38.953,56.584 -35.053,56.584 -33.753,56.584 -32.453,56.584 -31.153,56.584 -29.853,56.584 -28.553,56.584 -27.253,56.584 -25.953,56.584 -22.053,56.584 -20.753,56.584 -19.453,56.584 -18.153,56.584 -16.853,56.584 -14.253,56.584 -10.353,56.584 -9.053,56.584 -7.753,56.584 -6.453,56.584 -5.153,56.584 -3.853,56.584 -2.553,56.584 -1.253,56.584 0.047,56.584 1.347,56.584 2.647,56.584 3.947,56.584 5.247,56.584 7.847,56.584 9.147,56.584 10.447,56.584 11.747,56.584 14.347,56.584 15.647,56.584 22.147,56.584 39.047,56.584 40.347,56.584 41.647,56.584 42.947,56.584 44.247,56.584 67.647,56.584 76.747,56.584 81.947,56.584 83.247,56.584 85.847,56.584 87.147,56.584 88.447,56.584 89.747,56.584 91.047,56.584 92.347,56.584 93.647,56.584 94.947,56.584 98.847,56.584 -44.153,57.884 -42.853,57.884 -41.553,57.884 -40.253,57.884 -38.953,57.884 -31.153,57.884 -29.853,57.884 -28.553,57.884 -27.253,57.884 -25.953,57.884 -22.053,57.884 -20.753,57.884 -19.453,57.884 -18.153,57.884 -16.853,57.884 -11.653,57.884 -10.353,57.884 -9.053,57.884 -7.753,57.884 -6.453,57.884 -5.153,57.884 -3.853,57.884 -2.553,57.884 -1.253,57.884 0.047,57.884 1.347,57.884 2.647,57.884 3.947,57.884 5.247,57.884 7.847,57.884 9.147,57.884 10.447,57.884 11.747,57.884 20.847,57.884 22.147,57.884 31.247,57.884 32.547,57.884 39.047,57.884 42.947,57.884 44.247,57.884 45.547,57.884 46.847,57.884 48.147,57.884 49.447,57.884 50.747,57.884 52.047,57.884 53.347,57.884 54.647,57.884 59.847,57.884 61.147,57.884 70.247,57.884 76.747,57.884 81.947,57.884 83.247,57.884 85.847,57.884 87.147,57.884 88.447,57.884 89.747,57.884 91.047,57.884 92.347,57.884 93.647,57.884 94.947,57.884 98.847,57.884 -44.153,59.184 -42.853,59.184 -31.153,59.184 -29.853,59.184 -28.553,59.184 -27.253,59.184 -25.953,59.184 -22.053,59.184 -20.753,59.184 -19.453,59.184 -18.153,59.184 -16.853,59.184 -12.953,59.184 -11.653,59.184 -10.353,59.184 -9.053,59.184 -7.753,59.184 -6.453,59.184 -5.153,59.184 -3.853,59.184 -2.553,59.184 -1.253,59.184 0.047,59.184 1.347,59.184 2.647,59.184 3.947,59.184 13.047,59.184 14.347,59.184 19.547,59.184 20.847,59.184 22.147,59.184 32.547,59.184 39.047,59.184 42.947,59.184 44.247,59.184 45.547,59.184 46.847,59.184 48.147,59.184 49.447,59.184 50.747,59.184 52.047,59.184 53.347,59.184 54.647,59.184 55.947,59.184 57.247,59.184 58.547,59.184 59.847,59.184 61.147,59.184 68.947,59.184 70.247,59.184 76.747,59.184 81.947,59.184 83.247,59.184 85.847,59.184 87.147,59.184 88.447,59.184 89.747,59.184 91.047,59.184 92.347,59.184 93.647,59.184 94.947,59.184 98.847,59.184 -44.153,60.484 -42.853,60.484 -31.153,60.484 -29.853,60.484 -28.553,60.484 -27.253,60.484 -25.953,60.484 -22.053,60.484 -20.753,60.484 -19.453,60.484 -18.153,60.484 -14.253,60.484 -12.953,60.484 -11.653,60.484 -10.353,60.484 -9.053,60.484 -7.753,60.484 -6.453,60.484 -5.153,60.484 -3.853,60.484 -2.553,60.484 -1.253,60.484 44.247,60.484 45.547,60.484 46.847,60.484 48.147,60.484 49.447,60.484 50.747,60.484 52.047,60.484 53.347,60.484 54.647,60.484 59.847,60.484 61.147,60.484 67.647,60.484 68.947,60.484 70.247,60.484 81.947,60.484 83.247,60.484 85.847,60.484 87.147,60.484 88.447,60.484 89.747,60.484 91.047,60.484 92.347,60.484 93.647,60.484 94.947,60.484 98.847,60.484 -44.153,61.784 -42.853,61.784 -41.553,61.784 -33.753,61.784 -29.853,61.784 -28.553,61.784 -27.253,61.784 -25.953,61.784 -22.053,61.784 -20.753,61.784 -19.453,61.784 -12.953,61.784 -11.653,61.784 -10.353,61.784 -9.053,61.784 -7.753,61.784 -6.453,61.784 -5.153,61.784 -3.853,61.784 -2.553,61.784 -1.253,61.784 19.547,61.784 44.247,61.784 45.547,61.784 46.847,61.784 48.147,61.784 49.447,61.784 50.747,61.784 52.047,61.784 53.347,61.784 54.647,61.784 68.947,61.784 88.447,61.784 89.747,61.784 91.047,61.784 92.347,61.784 93.647,61.784 94.947,61.784 98.847,61.784 -44.153,63.084 -42.853,63.084 -41.553,63.084 -33.753,63.084 -32.453,63.084 -29.853,63.084 -28.553,63.084 -27.253,63.084 -25.953,63.084 -22.053,63.084 -20.753,63.084 -16.853,63.084 -15.553,63.084 -11.653,63.084 -10.353,63.084 -9.053,63.084 -7.753,63.084 -6.453,63.084 -5.153,63.084 -3.853,63.084 -2.553,63.084 -1.253,63.084 2.647,63.084 23.447,63.084 29.947,63.084 31.247,63.084 32.547,63.084 39.047,63.084 44.247,63.084 45.547,63.084 46.847,63.084 48.147,63.084 49.447,63.084 50.747,63.084 52.047,63.084 53.347,63.084 54.647,63.084 59.847,63.084 63.747,63.084 65.047,63.084 66.347,63.084 74.147,63.084 75.447,63.084 76.747,63.084 78.047,63.084 85.847,63.084 89.747,63.084 91.047,63.084 94.947,63.084 98.847,63.084 -44.153,64.384 -42.853,64.384 -41.553,64.384 -29.853,64.384 -28.553,64.384 -27.253,64.384 -25.953,64.384 -22.053,64.384 -20.753,64.384 -16.853,64.384 -15.553,64.384 -14.253,64.384 -10.353,64.384 -9.053,64.384 -7.753,64.384 -6.453,64.384 -5.153,64.384 -3.853,64.384 -2.553,64.384 -1.253,64.384 22.147,64.384 23.447,64.384 29.947,64.384 31.247,64.384 32.547,64.384 44.247,64.384 45.547,64.384 46.847,64.384 48.147,64.384 49.447,64.384 50.747,64.384 52.047,64.384 53.347,64.384 54.647,64.384 65.047,64.384 66.347,64.384 74.147,64.384 75.447,64.384 76.747,64.384 78.047,64.384 85.847,64.384 94.947,64.384 98.847,64.384 -44.153,65.684 -42.853,65.684 -41.553,65.684 -33.753,65.684 -29.853,65.684 -28.553,65.684 -27.253,65.684 -25.953,65.684 -22.053,65.684 -20.753,65.684 -16.853,65.684 -15.553,65.684 -14.253,65.684 -12.953,65.684 7.847,65.684 22.147,65.684 42.947,65.684 44.247,65.684 45.547,65.684 46.847,65.684 48.147,65.684 49.447,65.684 50.747,65.684 52.047,65.684 53.347,65.684 54.647,65.684 65.047,65.684 66.347,65.684 74.147,65.684 75.447,65.684 76.747,65.684 78.047,65.684 85.847,65.684 89.747,65.684 -44.153,66.984 -42.853,66.984 -41.553,66.984 -33.753,66.984 -28.553,66.984 -27.253,66.984 -25.953,66.984 -22.053,66.984 -20.753,66.984 -16.853,66.984 -15.553,66.984 -14.253,66.984 -12.953,66.984 -11.653,66.984 28.647,66.984 29.947,66.984 31.247,66.984 32.547,66.984 39.047,66.984 42.947,66.984 44.247,66.984 45.547,66.984 46.847,66.984 48.147,66.984 49.447,66.984 50.747,66.984 52.047,66.984 53.347,66.984 54.647,66.984 74.147,66.984 75.447,66.984 76.747,66.984 78.047,66.984 91.047,66.984 92.347,66.984 93.647,66.984 94.947,66.984 98.847,66.984 -44.153,68.284 -42.853,68.284 -41.553,68.284 -28.553,68.284 -27.253,68.284 -23.353,68.284 -22.053,68.284 -20.753,68.284 -16.853,68.284 -15.553,68.284 -14.253,68.284 -12.953,68.284 -11.653,68.284 -10.353,68.284 -9.053,68.284 -7.753,68.284 -6.453,68.284 -5.153,68.284 -3.853,68.284 -2.553,68.284 14.347,68.284 15.647,68.284 27.347,68.284 28.647,68.284 29.947,68.284 31.247,68.284 32.547,68.284 39.047,68.284 44.247,68.284 45.547,68.284 46.847,68.284 48.147,68.284 49.447,68.284 50.747,68.284 52.047,68.284 53.347,68.284 54.647,68.284 66.347,68.284 74.147,68.284 91.047,68.284 92.347,68.284 93.647,68.284 94.947,68.284 98.847,68.284 -44.153,69.584 -42.853,69.584 -41.553,69.584 -28.553,69.584 -24.653,69.584 -23.353,69.584 -22.053,69.584 -20.753,69.584 -16.853,69.584 -15.553,69.584 -14.253,69.584 -12.953,69.584 -11.653,69.584 -10.353,69.584 -9.053,69.584 -7.753,69.584 -6.453,69.584 -5.153,69.584 -3.853,69.584 -2.553,69.584 5.247,69.584 26.047,69.584 27.347,69.584 28.647,69.584 29.947,69.584 31.247,69.584 32.547,69.584 45.547,69.584 46.847,69.584 48.147,69.584 49.447,69.584 50.747,69.584 52.047,69.584 53.347,69.584 54.647,69.584 81.947,69.584 83.247,69.584 85.847,69.584 87.147,69.584 88.447,69.584 91.047,69.584 92.347,69.584 93.647,69.584 94.947,69.584 98.847,69.584 -44.153,70.884 -42.853,70.884 -41.553,70.884 -29.853,70.884 -28.553,70.884 -24.653,70.884 -23.353,70.884 -22.053,70.884 -20.753,70.884 -16.853,70.884 -15.553,70.884 -14.253,70.884 -12.953,70.884 -11.653,70.884 -10.353,70.884 -9.053,70.884 -7.753,70.884 -6.453,70.884 -5.153,70.884 -3.853,70.884 -2.553,70.884 3.947,70.884 5.247,70.884 7.847,70.884 24.747,70.884 45.547,70.884 46.847,70.884 48.147,70.884 49.447,70.884 50.747,70.884 52.047,70.884 53.347,70.884 54.647,70.884 59.847,70.884 61.147,70.884 62.447,70.884 63.747,70.884 71.547,70.884 81.947,70.884 83.247,70.884 88.447,70.884 89.747,70.884 98.847,70.884 -44.153,72.184 -42.853,72.184 -41.553,72.184 -38.953,72.184 -31.153,72.184 -29.853,72.184 -28.553,72.184 -24.653,72.184 -23.353,72.184 -22.053,72.184 -20.753,72.184 -16.853,72.184 -15.553,72.184 -14.253,72.184 -12.953,72.184 -11.653,72.184 -10.353,72.184 -9.053,72.184 -7.753,72.184 -6.453,72.184 -5.153,72.184 -3.853,72.184 -2.553,72.184 7.847,72.184 9.147,72.184 24.747,72.184 45.547,72.184 46.847,72.184 48.147,72.184 49.447,72.184 50.747,72.184 52.047,72.184 53.347,72.184 54.647,72.184 59.847,72.184 61.147,72.184 62.447,72.184 63.747,72.184 65.047,72.184 -44.153,73.484 -42.853,73.484 -38.953,73.484 -31.153,73.484 -29.853,73.484 -28.553,73.484 -24.653,73.484 -23.353,73.484 -22.053,73.484 -20.753,73.484 -16.853,73.484 -15.553,73.484 -14.253,73.484 -12.953,73.484 -11.653,73.484 -10.353,73.484 -9.053,73.484 -7.753,73.484 -6.453,73.484 -5.153,73.484 -3.853,73.484 -2.553,73.484 7.847,73.484 45.547,73.484 46.847,73.484 48.147,73.484 49.447,73.484 50.747,73.484 52.047,73.484 53.347,73.484 54.647,73.484 59.847,73.484 61.147,73.484 62.447,73.484 63.747,73.484 65.047,73.484 66.347,73.484 67.647,73.484 71.547,73.484 72.847,73.484 74.147,73.484 76.747,73.484 78.047,73.484 81.947,73.484 83.247,73.484 89.747,73.484 91.047,73.484 92.347,73.484 93.647,73.484 94.947,73.484 98.847,73.484 -44.153,74.784 -42.853,74.784 -38.953,74.784 -32.453,74.784 -31.153,74.784 -29.853,74.784 -28.553,74.784 -16.853,74.784 -15.553,74.784 -14.253,74.784 -12.953,74.784 -11.653,74.784 -10.353,74.784 -9.053,74.784 -7.753,74.784 -6.453,74.784 -5.153,74.784 -3.853,74.784 -2.553,74.784 31.247,74.784 53.347,74.784 54.647,74.784 74.147,74.784 76.747,74.784 78.047,74.784 81.947,74.784 83.247,74.784 93.647,74.784 98.847,74.784 -44.153,76.084 -42.853,76.084 -41.553,76.084 -38.953,76.084 -35.053,76.084 -33.753,76.084 -32.453,76.084 -31.153,76.084 -29.853,76.084 -28.553,76.084 -16.853,76.084 -15.553,76.084 -14.253,76.084 -12.953,76.084 -11.653,76.084 -10.353,76.084 -9.053,76.084 -7.753,76.084 -6.453,76.084 -5.153,76.084 -3.853,76.084 -2.553,76.084 0.047,76.084 1.347,76.084 26.047,76.084 27.347,76.084 28.647,76.084 29.947,76.084 31.247,76.084 32.547,76.084 74.147,76.084 76.747,76.084 78.047,76.084 81.947,76.084 83.247,76.084 98.847,76.084 -44.153,77.384 -42.853,77.384 -41.553,77.384 -38.953,77.384 -29.853,77.384 -28.553,77.384 -24.653,77.384 -23.353,77.384 -22.053,77.384 -20.753,77.384 -16.853,77.384 -15.553,77.384 -14.253,77.384 -12.953,77.384 -11.653,77.384 -10.353,77.384 -9.053,77.384 -7.753,77.384 -6.453,77.384 -5.153,77.384 -3.853,77.384 -2.553,77.384 0.047,77.384 1.347,77.384 10.447,77.384 48.147,77.384 85.847,77.384 87.147,77.384 88.447,77.384 96.247,77.384 97.547,77.384 98.847,77.384 -44.153,78.684 -42.853,78.684 -33.753,78.684 -32.453,78.684 -20.753,78.684 -16.853,78.684 -15.553,78.684 -14.253,78.684 -12.953,78.684 -11.653,78.684 -10.353,78.684 -9.053,78.684 -7.753,78.684 -6.453,78.684 -5.153,78.684 -3.853,78.684 -2.553,78.684 0.047,78.684 1.347,78.684 5.247,78.684 41.647,78.684 42.947,78.684 44.247,78.684 48.147,78.684 53.347,78.684 74.147,78.684 76.747,78.684 78.047,78.684 85.847,78.684 87.147,78.684 93.647,78.684 94.947,78.684 96.247,78.684 97.547,78.684 98.847,78.684 -44.153,79.984 -42.853,79.984 -41.553,79.984 -40.253,79.984 -38.953,79.984 -33.753,79.984 -32.453,79.984 -31.153,79.984 -20.753,79.984 -16.853,79.984 -15.553,79.984 -14.253,79.984 -12.953,79.984 -11.653,79.984 -10.353,79.984 -9.053,79.984 -7.753,79.984 -6.453,79.984 -5.153,79.984 -3.853,79.984 -2.553,79.984 1.347,79.984 26.047,79.984 27.347,79.984 28.647,79.984 29.947,79.984 74.147,79.984 76.747,79.984 78.047,79.984 92.347,79.984 93.647,79.984 94.947,79.984 96.247,79.984 -44.153,81.284 -42.853,81.284 -41.553,81.284 -40.253,81.284 -38.953,81.284 -37.653,81.284 -36.353,81.284 -35.053,81.284 -33.753,81.284 -32.453,81.284 -31.153,81.284 -20.753,81.284 -16.853,81.284 -15.553,81.284 -14.253,81.284 -12.953,81.284 -11.653,81.284 -6.453,81.284 -5.153,81.284 -3.853,81.284 -2.553,81.284 -1.253,81.284 2.647,81.284 3.947,81.284 14.347,81.284 15.647,81.284 26.047,81.284 27.347,81.284 28.647,81.284 29.947,81.284 74.147,81.284 76.747,81.284 78.047,81.284 92.347,81.284 93.647,81.284 94.947,81.284 96.247,81.284 -44.153,82.584 -42.853,82.584 -41.553,82.584 -40.253,82.584 -38.953,82.584 -37.653,82.584 -36.353,82.584 -35.053,82.584 -33.753,82.584 -32.453,82.584 -31.153,82.584 -29.853,82.584 -28.553,82.584 -27.253,82.584 -20.753,82.584 -16.853,82.584 -15.553,82.584 -14.253,82.584 -12.953,82.584 -11.653,82.584 -10.353,82.584 -6.453,82.584 -5.153,82.584 -3.853,82.584 -2.553,82.584 -1.253,82.584 0.047,82.584 3.947,82.584 16.947,82.584 26.047,82.584 52.047,82.584 53.347,82.584 74.147,82.584 76.747,82.584 78.047,82.584 81.947,82.584 87.147,82.584 88.447,82.584 -40.253,83.884 -38.953,83.884 -37.653,83.884 -36.353,83.884 -35.053,83.884 -29.853,83.884 -28.553,83.884 -27.253,83.884 -25.953,83.884 -24.653,83.884 -23.353,83.884 -22.053,83.884 -20.753,83.884 15.647,83.884 74.147,83.884 76.747,83.884 78.047,83.884 81.947,83.884 83.247,83.884 85.847,83.884 87.147,83.884 88.447,83.884 89.747,83.884 91.047,83.884 92.347,83.884 93.647,83.884 94.947,83.884 96.247,83.884 97.547,83.884 98.847,83.884 -40.253,85.184 -38.953,85.184 -37.653,85.184 -36.353,85.184 -35.053,85.184 -29.853,85.184 -28.553,85.184 -27.253,85.184 -20.753,85.184 19.547,85.184 27.347,85.184 28.647,85.184 29.947,85.184 31.247,85.184 32.547,85.184 49.447,85.184 50.747,85.184 74.147,85.184 78.047,85.184 81.947,85.184 83.247,85.184 85.847,85.184 87.147,85.184 88.447,85.184 89.747,85.184 91.047,85.184 92.347,85.184 93.647,85.184 94.947,85.184 96.247,85.184 97.547,85.184 98.847,85.184 -40.253,86.484 -38.953,86.484 -37.653,86.484 -36.353,86.484 -35.053,86.484 -29.853,86.484 -28.553,86.484 -27.253,86.484 -20.753,86.484 -16.853,86.484 -15.553,86.484 -14.253,86.484 -12.953,86.484 -11.653,86.484 -10.353,86.484 -9.053,86.484 -7.753,86.484 -6.453,86.484 -5.153,86.484 -3.853,86.484 -2.553,86.484 -1.253,86.484 0.047,86.484 1.347,86.484 2.647,86.484 3.947,86.484 10.447,86.484 18.247,86.484 19.547,86.484 31.247,86.484 32.547,86.484 49.447,86.484 50.747,86.484 52.047,86.484 53.347,86.484 74.147,86.484 75.447,86.484 81.947,86.484 83.247,86.484 85.847,86.484 87.147,86.484 88.447,86.484 89.747,86.484 91.047,86.484 92.347,86.484 93.647,86.484 94.947,86.484 96.247,86.484 97.547,86.484 98.847,86.484 -44.153,87.784 -42.853,87.784 -41.553,87.784 -40.253,87.784 -38.953,87.784 -37.653,87.784 -36.353,87.784 -35.053,87.784 -33.753,87.784 -32.453,87.784 -31.153,87.784 -29.853,87.784 -28.553,87.784 -20.753,87.784 -16.853,87.784 2.647,87.784 3.947,87.784 5.247,87.784 18.247,87.784 59.847,87.784 61.147,87.784 62.447,87.784 63.747,87.784 65.047,87.784 66.347,87.784 67.647,87.784 68.947,87.784 70.247,87.784 71.547,87.784 72.847,87.784 74.147,87.784 75.447,87.784 -44.153,89.084 -42.853,89.084 -41.553,89.084 -35.053,89.084 -33.753,89.084 -32.453,89.084 -31.153,89.084 -29.853,89.084 -28.553,89.084 -24.653,89.084 -20.753,89.084 -16.853,89.084 2.647,89.084 3.947,89.084 5.247,89.084 59.847,89.084 61.147,89.084 62.447,89.084 63.747,89.084 65.047,89.084 66.347,89.084 67.647,89.084 68.947,89.084 78.047,89.084 83.247,89.084 85.847,89.084 87.147,89.084 88.447,89.084 94.947,89.084 96.247,89.084 97.547,89.084 -44.153,90.384 -42.853,90.384 -41.553,90.384 -35.053,90.384 -33.753,90.384 -32.453,90.384 -31.153,90.384 -29.853,90.384 -28.553,90.384 -27.253,90.384 -24.653,90.384 -20.753,90.384 -16.853,90.384 2.647,90.384 3.947,90.384 5.247,90.384 29.947,90.384 53.347,90.384 54.647,90.384 59.847,90.384 61.147,90.384 62.447,90.384 63.747,90.384 65.047,90.384 66.347,90.384 67.647,90.384 71.547,90.384 72.847,90.384 74.147,90.384 75.447,90.384 76.747,90.384 78.047,90.384 80.647,90.384 -44.153,91.684 -42.853,91.684 -41.553,91.684 -35.053,91.684 -33.753,91.684 -32.453,91.684 -31.153,91.684 -29.853,91.684 -28.553,91.684 -27.253,91.684 -24.653,91.684 -16.853,91.684 2.647,91.684 3.947,91.684 5.247,91.684 10.447,91.684 29.947,91.684 53.347,91.684 54.647,91.684 55.947,91.684 57.247,91.684 58.547,91.684 67.647,91.684 70.247,91.684 76.747,91.684 78.047,91.684 80.647,91.684 81.947,91.684 -44.153,92.984 -42.853,92.984 -41.553,92.984 -35.053,92.984 -18.153,92.984 -16.853,92.984 2.647,92.984 3.947,92.984 10.447,92.984 29.947,92.984 67.647,92.984 70.247,92.984 76.747,92.984 78.047,92.984 80.647,92.984 81.947,92.984 83.247,92.984 85.847,92.984 92.347,92.984 -44.153,94.284 -42.853,94.284 -31.153,94.284 -29.853,94.284 -28.553,94.284 -27.253,94.284 -22.053,94.284 -20.753,94.284 -19.453,94.284 -18.153,94.284 -16.853,94.284 3.947,94.284 5.247,94.284 11.747,94.284 39.047,94.284 40.347,94.284 41.647,94.284 42.947,94.284 44.247,94.284 67.647,94.284 70.247,94.284 76.747,94.284 78.047,94.284 81.947,94.284 83.247,94.284 85.847,94.284 87.147,94.284 89.747,94.284 92.347,94.284 93.647,94.284 94.947,94.284 -44.153,95.584 -42.853,95.584 -31.153,95.584 -29.853,95.584 -28.553,95.584 -23.353,95.584 -22.053,95.584 -20.753,95.584 -19.453,95.584 -18.153,95.584 -16.853,95.584 39.047,95.584 40.347,95.584 41.647,95.584 42.947,95.584 44.247,95.584 45.547,95.584 46.847,95.584 48.147,95.584 49.447,95.584 50.747,95.584 52.047,95.584 67.647,95.584 70.247,95.584 76.747,95.584 78.047,95.584 79.347,95.584 91.047,95.584 92.347,95.584 93.647,95.584 94.947,95.584 98.847,95.584 -44.153,96.884 -42.853,96.884 -41.553,96.884 -40.253,96.884 -37.653,96.884 -36.353,96.884 -35.053,96.884 -31.153,96.884 -29.853,96.884 -28.553,96.884 -24.653,96.884 -23.353,96.884 -22.053,96.884 -20.753,96.884 -19.453,96.884 -18.153,96.884 -16.853,96.884 45.547,96.884 46.847,96.884 48.147,96.884 49.447,96.884 50.747,96.884 52.047,96.884 53.347,96.884 54.647,96.884 67.647,96.884 70.247,96.884 76.747,96.884 78.047,96.884 79.347,96.884 80.647,96.884 81.947,96.884 83.247,96.884 85.847,96.884 87.147,96.884 89.747,96.884 91.047,96.884 92.347,96.884 93.647,96.884 94.947,96.884 98.847,96.884 -44.153,98.184 -42.853,98.184 -41.553,98.184 -40.253,98.184 -36.353,98.184 -35.053,98.184 -33.753,98.184 -31.153,98.184 -29.853,98.184 -28.553,98.184 -24.653,98.184 -23.353,98.184 -22.053,98.184 -20.753,98.184 -19.453,98.184 -18.153,98.184 -16.853,98.184 24.747,98.184 67.647,98.184 70.247,98.184 76.747,98.184 78.047,98.184 79.347,98.184 80.647,98.184 81.947,98.184 83.247,98.184 85.847,98.184 87.147,98.184 88.447,98.184 89.747,98.184 91.047,98.184 92.347,98.184 93.647,98.184 94.947,98.184 96.247,98.184 97.547,98.184 98.847,98.184 -44.153,99.484 -42.853,99.484 -41.553,99.484 -40.253,99.484 -38.953,99.484 -31.153,99.484 -29.853,99.484 -28.553,99.484 -24.653,99.484 -23.353,99.484 -22.053,99.484 -20.753,99.484 -19.453,99.484 -18.153,99.484 -16.853,99.484 13.047,99.484 14.347,99.484 22.147,99.484 24.747,99.484 26.047,99.484 27.347,99.484 28.647,99.484 29.947,99.484 31.247,99.484 32.547,99.484 45.547,99.484 67.647,99.484 70.247,99.484 85.847,99.484 87.147,99.484 88.447,99.484 89.747,99.484 91.047,99.484 92.347,99.484 93.647,99.484 94.947,99.484 96.247,99.484 97.547,99.484 98.847,99.484 -44.153,100.784 -42.853,100.784 -41.553,100.784 -40.253,100.784 -38.953,100.784 -37.653,100.784 -36.353,100.784 -35.053,100.784 -31.153,100.784 -29.853,100.784 -28.553,100.784 -24.653,100.784 -23.353,100.784 -19.453,100.784 -18.153,100.784 -16.853,100.784 24.747,100.784 26.047,100.784 27.347,100.784 28.647,100.784 29.947,100.784 31.247,100.784 32.547,100.784 45.547,100.784 46.847,100.784 48.147,100.784 49.447,100.784 50.747,100.784 52.047,100.784 53.347,100.784 54.647,100.784 67.647,100.784 70.247,100.784 85.847,100.784 87.147,100.784 88.447,100.784 89.747,100.784 91.047,100.784 92.347,100.784 93.647,100.784 94.947,100.784 96.247,100.784 97.547,100.784 98.847,100.784 -44.153,102.084 -42.853,102.084 -41.553,102.084 -40.253,102.084 -38.953,102.084 -37.653,102.084 -36.353,102.084 -35.053,102.084 -32.453,102.084 -31.153,102.084 -29.853,102.084 -28.553,102.084 -24.653,102.084 -23.353,102.084 -19.453,102.084 -18.153,102.084 -16.853,102.084 45.547,102.084 46.847,102.084 48.147,102.084 49.447,102.084 50.747,102.084 52.047,102.084 53.347,102.084 54.647,102.084 63.747,102.084 65.047,102.084 67.647,102.084 72.847,102.084 79.347,102.084 80.647,102.084 81.947,102.084 83.247,102.084 85.847,102.084 87.147,102.084 88.447,102.084 89.747,102.084 91.047,102.084 92.347,102.084 93.647,102.084 94.947,102.084 96.247,102.084 97.547,102.084 98.847,102.084 -44.153,103.384 -42.853,103.384 -41.553,103.384 -36.353,103.384 -35.053,103.384 -29.853,103.384 -28.553,103.384 -24.653,103.384 -23.353,103.384 -19.453,103.384 -18.153,103.384 -16.853,103.384 45.547,103.384 46.847,103.384 48.147,103.384 49.447,103.384 50.747,103.384 52.047,103.384 53.347,103.384 54.647,103.384 63.747,103.384 65.047,103.384 72.847,103.384 74.147,103.384 75.447,103.384 76.747,103.384 78.047,103.384 79.347,103.384 80.647,103.384 81.947,103.384 83.247,103.384 85.847,103.384 91.047,103.384 92.347,103.384 93.647,103.384 94.947,103.384 96.247,103.384 97.547,103.384 -44.153,104.684 -42.853,104.684 -36.353,104.684 -35.053,104.684 -29.853,104.684 -28.553,104.684 -24.653,104.684 -23.353,104.684 -22.053,104.684 -20.753,104.684 -19.453,104.684 -18.153,104.684 -16.853,104.684 -15.553,104.684 39.047,104.684 42.947,104.684 44.247,104.684 45.547,104.684 46.847,104.684 48.147,104.684 49.447,104.684 50.747,104.684 52.047,104.684 53.347,104.684 54.647,104.684 63.747,104.684 65.047,104.684 66.347,104.684 72.847,104.684 74.147,104.684 75.447,104.684 76.747,104.684 78.047,104.684 79.347,104.684 80.647,104.684 81.947,104.684 83.247,104.684 85.847,104.684 91.047,104.684 92.347,104.684 93.647,104.684 94.947,104.684 96.247,104.684 97.547,104.684 -44.153,105.984 -42.853,105.984 -41.553,105.984 -35.053,105.984 -29.853,105.984 -28.553,105.984 -24.653,105.984 -23.353,105.984 -22.053,105.984 -20.753,105.984 -19.453,105.984 -18.153,105.984 -16.853,105.984 -15.553,105.984 39.047,105.984 40.347,105.984 41.647,105.984 42.947,105.984 44.247,105.984 45.547,105.984 46.847,105.984 48.147,105.984 49.447,105.984 50.747,105.984 52.047,105.984 53.347,105.984 54.647,105.984 65.047,105.984 66.347,105.984 74.147,105.984 75.447,105.984 79.347,105.984 80.647,105.984 81.947,105.984 83.247,105.984 85.847,105.984 91.047,105.984 92.347,105.984 93.647,105.984 94.947,105.984 96.247,105.984 97.547,105.984 -44.153,107.284 -42.853,107.284 -41.553,107.284 -35.053,107.284 -31.153,107.284 -29.853,107.284 -25.953,107.284 -24.653,107.284 -23.353,107.284 -22.053,107.284 -20.753,107.284 -19.453,107.284 -18.153,107.284 -16.853,107.284 -15.553,107.284 -1.253,107.284 1.347,107.284 39.047,107.284 40.347,107.284 41.647,107.284 42.947,107.284 44.247,107.284 45.547,107.284 46.847,107.284 48.147,107.284 49.447,107.284 50.747,107.284 52.047,107.284 53.347,107.284 54.647,107.284 85.847,107.284 87.147,107.284 88.447,107.284 89.747,107.284 91.047,107.284 92.347,107.284 93.647,107.284 94.947,107.284 96.247,107.284 97.547,107.284 98.847,107.284 -44.153,108.584 -42.853,108.584 -41.553,108.584 -35.053,108.584 -32.453,108.584 -31.153,108.584 -27.253,108.584 -25.953,108.584 -24.653,108.584 -23.353,108.584 -22.053,108.584 -20.753,108.584 -19.453,108.584 -18.153,108.584 -16.853,108.584 -15.553,108.584 -1.253,108.584 0.047,108.584 1.347,108.584 2.647,108.584 3.947,108.584 5.247,108.584 6.547,108.584 19.547,108.584 20.847,108.584 22.147,108.584 23.447,108.584 24.747,108.584 26.047,108.584 27.347,108.584 28.647,108.584 29.947,108.584 31.247,108.584 39.047,108.584 40.347,108.584 41.647,108.584 42.947,108.584 44.247,108.584 45.547,108.584 46.847,108.584 48.147,108.584 49.447,108.584 50.747,108.584 52.047,108.584 53.347,108.584 54.647,108.584 79.347,108.584 80.647,108.584 81.947,108.584 83.247,108.584 84.547,108.584 85.847,108.584 87.147,108.584 88.447,108.584 89.747,108.584 91.047,108.584 92.347,108.584 93.647,108.584 94.947,108.584 96.247,108.584 97.547,108.584 98.847,108.584 -44.153,109.884 -42.853,109.884 -41.553,109.884 -28.553,109.884 -27.253,109.884 -25.953,109.884 -24.653,109.884 -23.353,109.884 -22.053,109.884 -20.753,109.884 -19.453,109.884 -18.153,109.884 -16.853,109.884 -15.553,109.884 -1.253,109.884 0.047,109.884 1.347,109.884 2.647,109.884 3.947,109.884 5.247,109.884 7.847,109.884 19.547,109.884 20.847,109.884 22.147,109.884 39.047,109.884 40.347,109.884 41.647,109.884 42.947,109.884 44.247,109.884 45.547,109.884 46.847,109.884 48.147,109.884 49.447,109.884 50.747,109.884 52.047,109.884 53.347,109.884 54.647,109.884 59.847,109.884 61.147,109.884 62.447,109.884 -44.153,111.184 -42.853,111.184 -41.553,111.184 -28.553,111.184 -27.253,111.184 -25.953,111.184 -24.653,111.184 -23.353,111.184 -22.053,111.184 -20.753,111.184 -19.453,111.184 -18.153,111.184 -16.853,111.184 -15.553,111.184 -1.253,111.184 0.047,111.184 1.347,111.184 2.647,111.184 3.947,111.184 5.247,111.184 7.847,111.184 11.747,111.184 13.047,111.184 14.347,111.184 19.547,111.184 20.847,111.184 22.147,111.184 53.347,111.184 54.647,111.184 59.847,111.184 61.147,111.184 62.447,111.184 63.747,111.184 65.047,111.184 66.347,111.184 -44.153,112.484 -42.853,112.484 -41.553,112.484 -40.253,112.484 -38.953,112.484 -37.653,112.484 -36.353,112.484 -35.053,112.484 -33.753,112.484 -32.453,112.484 -28.553,112.484 -27.253,112.484 -25.953,112.484 -24.653,112.484 -23.353,112.484 -22.053,112.484 -20.753,112.484 -19.453,112.484 -18.153,112.484 -16.853,112.484 -15.553,112.484 -1.253,112.484 5.247,112.484 7.847,112.484 9.147,112.484 10.447,112.484 11.747,112.484 13.047,112.484 14.347,112.484 20.847,112.484 22.147,112.484 23.447,112.484 24.747,112.484 44.247,112.484 45.547,112.484 46.847,112.484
